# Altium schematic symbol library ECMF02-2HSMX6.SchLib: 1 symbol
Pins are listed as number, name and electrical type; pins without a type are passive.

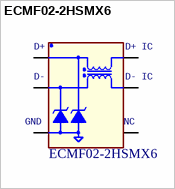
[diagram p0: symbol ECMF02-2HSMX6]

## ECMF02-2HSMX6
designator U?
footprint ST_QFN50P170X150X55-6L-ASYM (Footprint not found)
pins: 1 D+, 2 D-, 3 GND, 4 NC, 5 D- IC, 6 D+ IC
